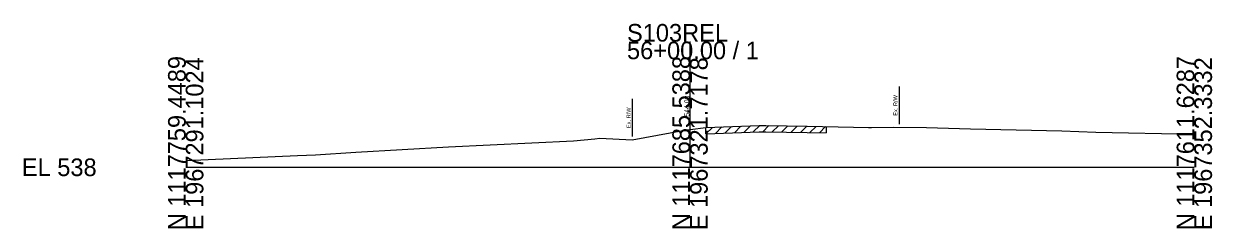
# Model space of a CAD drawing. Extents: x -26 to 163, y -10 to 24518.
# Drawn here: x -25.7 to 162.8, y 6490.3 to 6522.8 of the extents above; entities that cross this region are included whole.
import ezdxf

# ---------------------------------------------------------------- set-up
doc = ezdxf.new("R2010")
doc.units = 0
for name, color, linetype in [('RD_GPK_XS_Cell', 7, 'Continuous'), ('RD_XS_ExGround', 7, 'Continuous'), ('RD_XS_ExPaveRet', 7, 'Continuous'), ('RD_XS_ExRW', 7, 'Continuous'), ('RD_XS_TX_Elev_EX', 7, 'Continuous')]:
    doc.layers.add(name, color=color, linetype=linetype)

msp = doc.modelspace()

# ---------------------------------------------------------------- linework, layer by layer
at = {"layer": 'RD_GPK_XS_Cell'}
for p, q in [((80, 6500), (80, 6519.98)), ((0, 6500), (80, 6500)), ((80, 6500), (160, 6500))]:
    msp.add_line(p, q, dxfattribs=at)
at = {"layer": 'RD_XS_ExGround'}
msp.add_lwpolyline([(0, 6501.07), (17.75, 6501.86), (20.57, 6501.98), (27.01, 6502.43), (41.68, 6503.27), (61.49, 6504.18), (64.89, 6504.55), (65.68, 6504.63), (70.82, 6504.39), (78.84, 6505.85), (79.21, 6505.95), (80, 6506.03), (82.53, 6506.31), (90.97, 6506.65), (91.28, 6506.66), (92.01, 6506.63), (98.6, 6506.52), (105.92, 6506.38), (108.32, 6506.33), (108.78, 6506.34), (112.26, 6506.36), (117.5, 6506.32), (124.48, 6506.11), (139, 6505.79), (144.4, 6505.6), (160, 6505.28)], dxfattribs=at)
at = {"layer": 'RD_XS_ExPaveRet'}
for p, q in [((82.53, 6505.31), (83.57, 6506.35)), ((82.53, 6505.31), (82.53, 6506.31)), ((84.03, 6505.37), (85.07, 6506.41)), ((85.53, 6505.43), (86.57, 6506.47)), ((87.03, 6505.49), (88.07, 6506.53)), ((88.53, 6505.55), (89.57, 6506.59)), ((90.03, 6505.61), (91.07, 6506.65)), ((91.53, 6505.65), (92.5, 6506.62)), ((93.03, 6505.61), (94.01, 6506.59)), ((94.53, 6505.59), (95.51, 6506.57)), ((96.03, 6505.56), (97.01, 6506.55)), ((97.53, 6505.54), (98.51, 6506.52)), ((99.03, 6505.51), (100.01, 6506.49)), ((100.53, 6505.48), (101.51, 6506.46)), ((101.57, 6506.46), (101.57, 6505.46)), ((82.53, 6505.31), (90.97, 6505.65)), ((90.97, 6505.65), (91.28, 6505.66)), ((91.28, 6505.66), (92.01, 6505.63)), ((92.01, 6505.63), (98.6, 6505.52)), ((98.6, 6505.52), (101.57, 6505.46))]:
    msp.add_line(p, q, dxfattribs=at)
at = {"layer": 'RD_XS_ExRW'}
for p, q in [((113.16, 6512.85), (113.16, 6506.85)), ((70.83, 6510.89), (70.83, 6504.89))]:
    msp.add_line(p, q, dxfattribs=at)

# ---------------------------------------------------------------- texts
at = {"layer": 'RD_GPK_XS_Cell'}
for s, p in [('S103REL', (70, 6519.98)), ('56+00.00 / 1', (70, 6517.18)), ('EL 538', (-26, 6498.6))]:
    msp.add_text(s, height=2.8, dxfattribs=at).set_placement(p)
for s, p in [('N 1117759.4489', (0, 6490)), ('E 1967291.1024', (2.8, 6490)), ('N 1117685.5388', (80, 6490)), ('E 1967321.7178', (82.8, 6490)), ('N 1117611.6287', (160, 6490)), ('E 1967352.3332', (162.8, 6490))]:
    msp.add_text(s, height=2.8, rotation=90, dxfattribs=at).set_placement(p)
at = {"layer": 'RD_XS_ExRW'}
for p in [(112.91, 6508.19), (70.58, 6506.23)]:
    msp.add_text('Ex. R/W ', height=0.65, rotation=90, dxfattribs=at).set_placement(p)
at = {"layer": 'RD_XS_TX_Elev_EX'}
msp.add_text('544.03', height=0.8, rotation=90, dxfattribs=at).set_placement((79.9, 6508.03))

doc.saveas('drawing.dxf')
